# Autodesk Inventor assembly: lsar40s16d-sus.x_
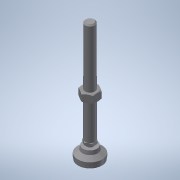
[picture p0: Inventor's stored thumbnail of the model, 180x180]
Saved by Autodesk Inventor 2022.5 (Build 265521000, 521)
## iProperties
Part Number: lsar40s16d-sus.x_
Material: 一般
Document SubType Name: Assembly
Designer: ImaoCorp
Sending System: SOLIDWORKS 2017-2017317
MC: AMD64
MC_MODEL: Intel64 Family 6 Model 60 Stepping 3, GenuineIntel
OS: Windows_NT
FRU: Parasolid Version 29.0, build 201,  4-17-2017
FORMAT: text
GUISE: transmit
KEY: lsar40s16d-sus
FILE: lsar40s16d-sus.x_t
DATE: Mon Jul 01 18:01:47 2019
Author: ImaoCorp
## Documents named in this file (3)
- X:\14_SW2022-Inv2022\00_全2023-1023新製品(TCC)まで\l\lsar40s16d-sus\LSAR40S16D-SUS.iam
- X:\14_SW2022-Inv2022\00_全2023-1023新製品(TCC)まで\l\lsar40s16d-sus\lsar40s16d-sus_01.ipt
- X:\14_SW2022-Inv2022\00_全2023-1023新製品(TCC)まで\l\lsar40s16d-sus\lsar40s16d-sus_02.ipt
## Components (2 placed, 2 different names)
1. lsar40s16d-sus_01
2. lsar40s16d-sus_02
